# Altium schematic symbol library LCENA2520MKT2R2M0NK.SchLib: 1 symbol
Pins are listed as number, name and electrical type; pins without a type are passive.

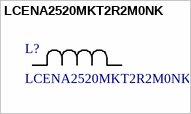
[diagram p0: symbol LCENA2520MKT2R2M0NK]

## LCENA2520MKT2R2M0NK
designator L?
No Description Available; Manufacturer_Name: TAIYO YUDEN
footprint IND_LCEN_2520MK_TAY
pins: 1, 2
